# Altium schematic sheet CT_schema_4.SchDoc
size 349 x 342 mm
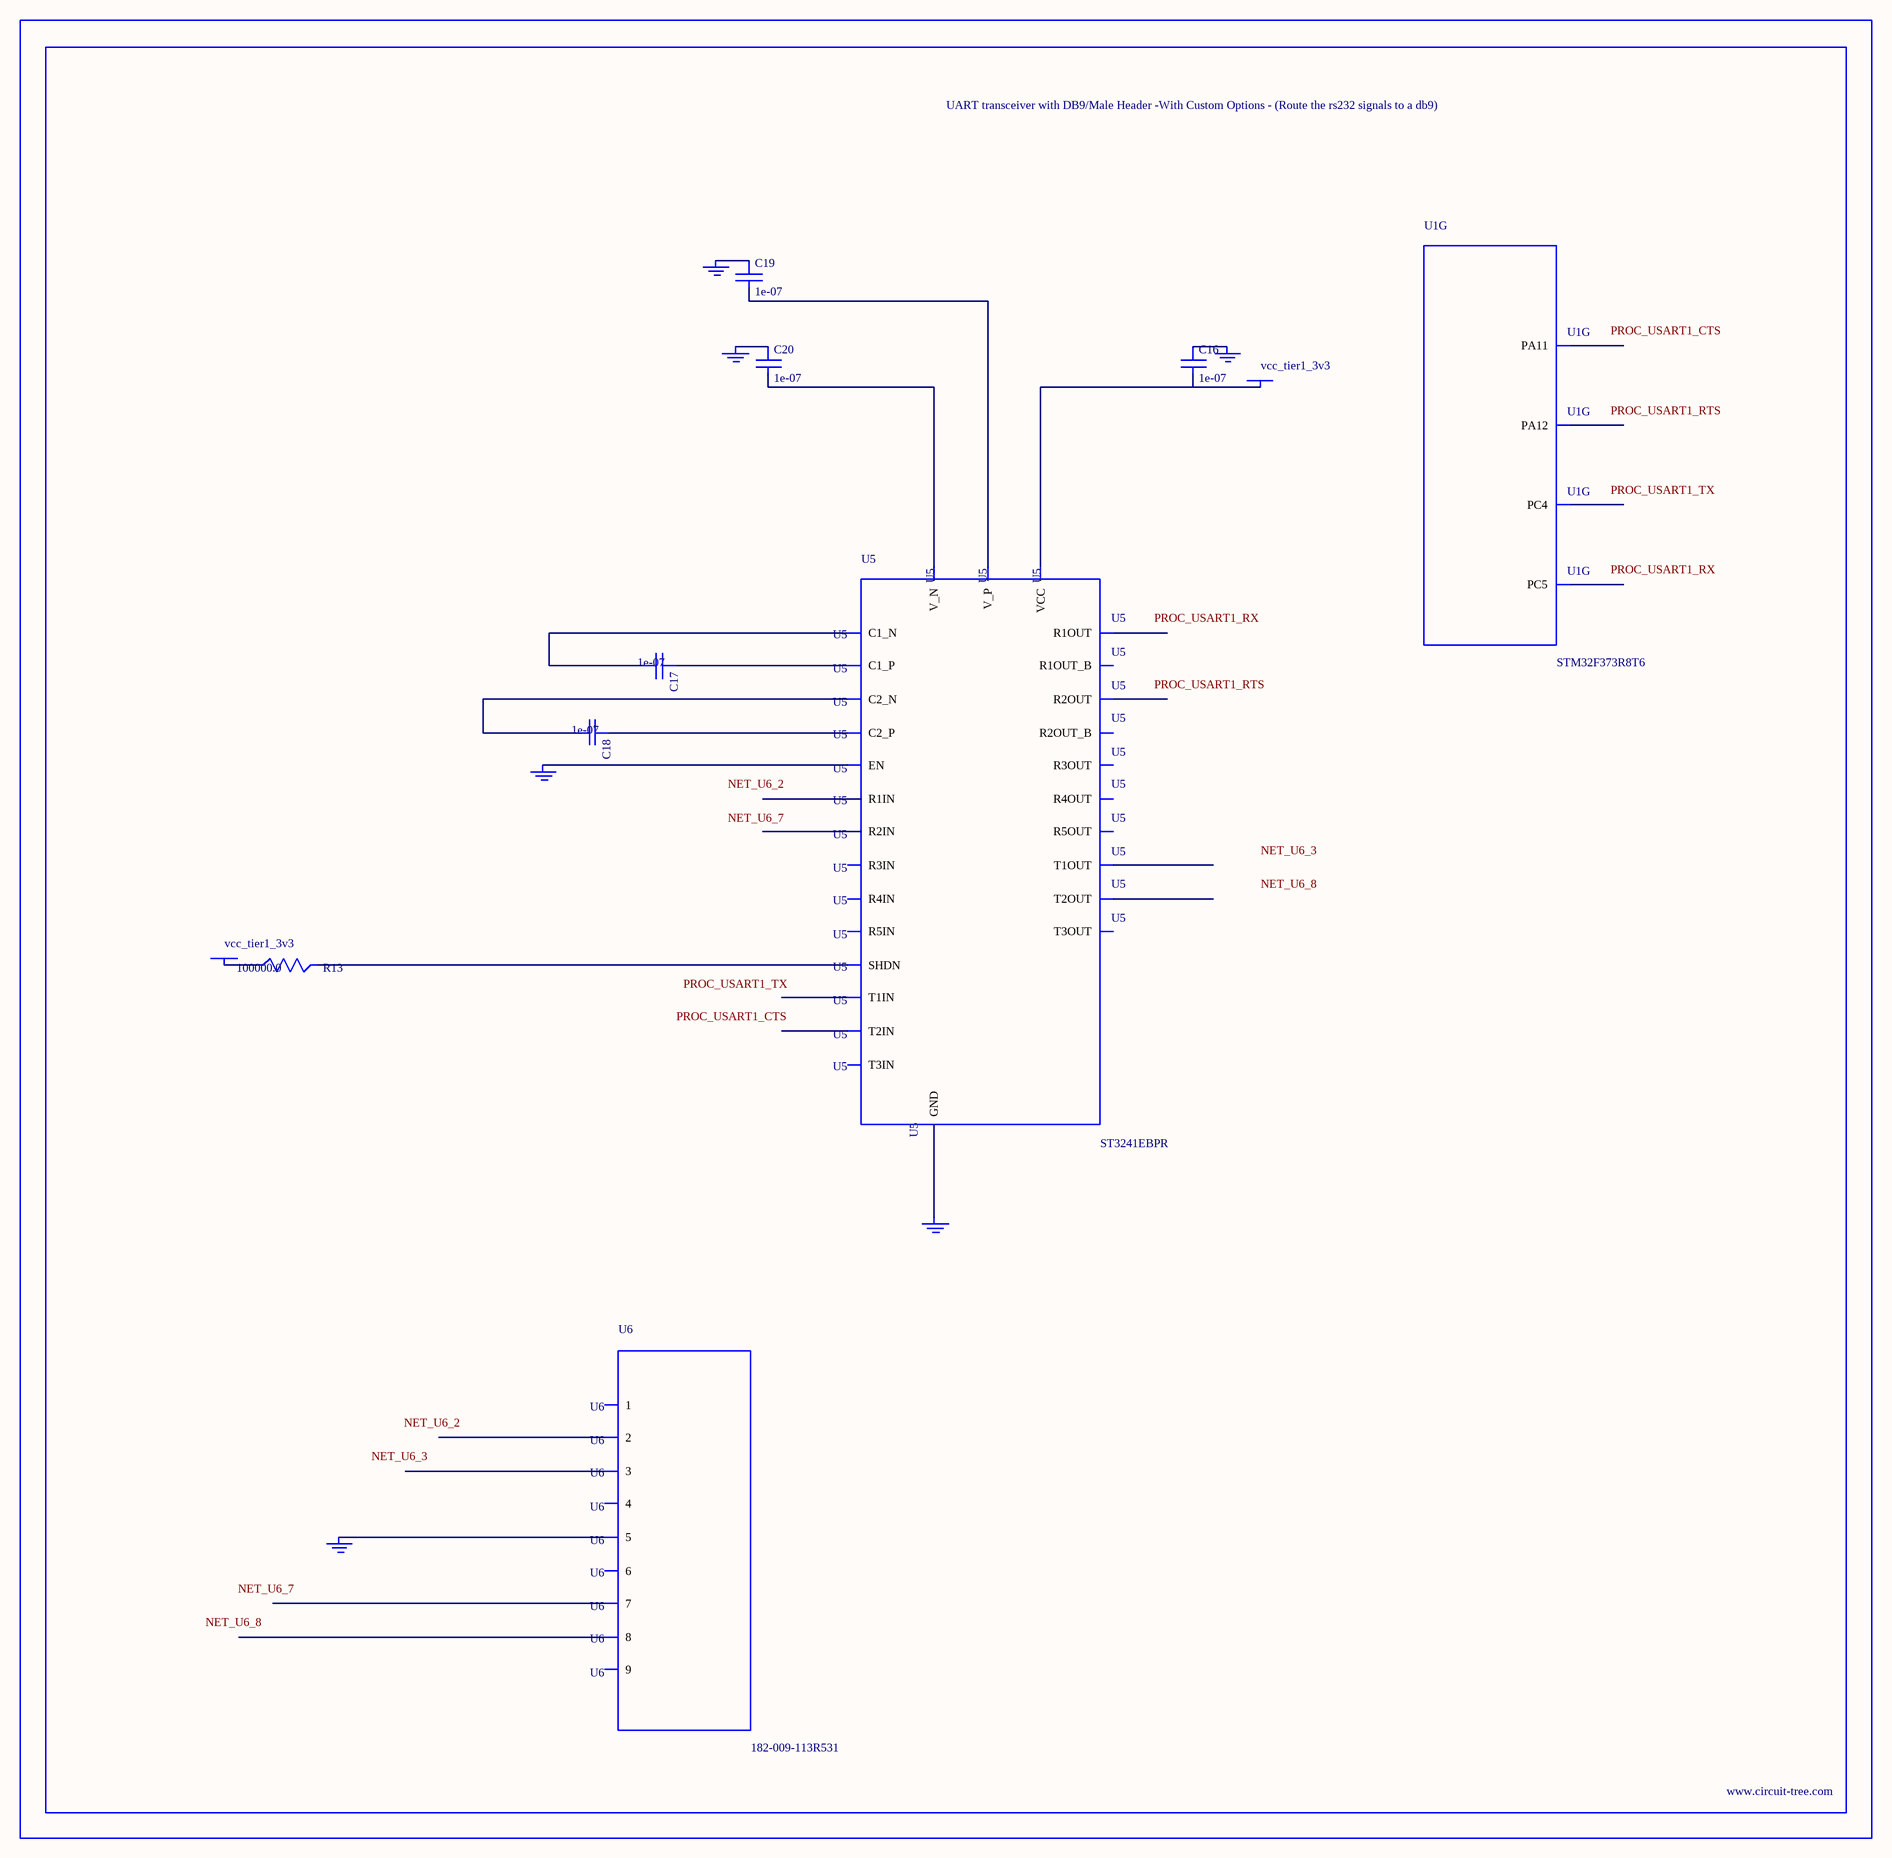
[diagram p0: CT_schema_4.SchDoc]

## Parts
BORDER3  (no value)
C16  1e-07  [C0402]
C17  1e-07  [C0402]
C18  1e-07  [C0402]
C19  1e-07  [C0402]
C20  1e-07  [C0402]
GND_INSTANCE_3_0  (no value)
GND_INSTANCE_3_1  (no value)
GND_INSTANCE_3_2  (no value)
GND_INSTANCE_3_3  (no value)
GND_INSTANCE_3_4  (no value)
GND_INSTANCE_3_5  (no value)
POWER_INSTANCE_3_0  vcc_tier1_3v3
POWER_INSTANCE_3_1  vcc_tier1_3v3
R13  100000.0  [R0603]
U1  STM32F373R8T6  [LQFP64]  (part G of 7)
U5  ST3241EBPR  [SSOP-28]
U6  182-009-113R531  [182-009-MALE]

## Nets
NetC16_1: C16.1 GND_INSTANCE_3_2.0(GND)
NetC16_2: C16.2 POWER_INSTANCE_3_1.0(PWR) U5.26(VCC)
NetC17_1: C17.1 U5.28(C1_P)
NetC17_2: C17.2 U5.24(C1_N)
NetC18_1: C18.1 U5.1(C2_P)
NetC18_2: C18.2 U5.2(C2_N)
NetC19_1: C19.1 GND_INSTANCE_3_3.0(GND)
NetC19_2: C19.2 U5.27(V_P)
NetC20_1: C20.1 GND_INSTANCE_3_0.0(GND)
NetC20_2: C20.2 U5.3(V_N)
NetGND_INSTANCE_3_1_0: GND_INSTANCE_3_1.0(GND) U5.23(EN)
NetGND_INSTANCE_3_4_0: GND_INSTANCE_3_4.0(GND) U5.25(GND)
NetGND_INSTANCE_3_5_0: GND_INSTANCE_3_5.0(GND) U6.5
NetPOWER_INSTANCE_3_0_0: POWER_INSTANCE_3_0.0(PWR) R13.1
NetR13_2: R13.2 U5.22(SHDN)

Not connected (* = marked no-connect by the designer): U1 24(PC4) 25(PC5) 44(PA11) 45(PA12); U5 4(R1IN) 5(R2IN) 6(R3IN) 7(R4IN) 8(R5IN) 9(T1OUT) 10(T2OUT) 11(T3OUT) 12(T3IN) 13(T2IN) 14(T1IN) 15(R5OUT) 16(R4OUT) 17(R3OUT) 18(R2OUT) 19(R1OUT) 20(R2OUT_B) 21(R1OUT_B); U6 1 2 3 4 6 7 8 9

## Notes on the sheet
- Labels drawn without touching a wire or pin: NET_U6_2, NET_U6_3, NET_U6_7, NET_U6_8, PROC_USART1_CTS, PROC_USART1_RTS, PROC_USART1_RX, PROC_USART1_TX

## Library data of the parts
BORDER3 = BORDER_PAGE3
C16-C20 = C0402C104K3RACTU
GND_INSTANCE_3_0-GND_INSTANCE_3_5 = GND
POWER_INSTANCE_3_0 POWER_INSTANCE_3_1 = PWR
R13 = RC0603JR-07100KL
